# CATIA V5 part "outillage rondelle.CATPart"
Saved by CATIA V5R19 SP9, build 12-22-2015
Part number: outillage rondelle
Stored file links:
  Z:\fausse table rondelle-20220905T211342Z-001\fausse table rondelle\outillage rondelle.CATPart
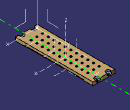
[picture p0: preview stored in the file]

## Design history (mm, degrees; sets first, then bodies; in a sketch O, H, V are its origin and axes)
AxisSystem1: origin (0, 0, 0), X (1, 0, 0), Y (0, 1, 0), Z (0, 0, 1)
AxisSystem2: origin (-48.5, -174, 0), X (1, 0, 0), Y (0, 1, 0), Z (0, 0, 1)
Set1 "GEOCN"
  Point1: (0, -3, 0), relative to vertex [face of Pad1 from Sketch1.L3 | face of Pad1 from Sketch1.L2 | start face of Pad1], in AxisSystem1
Body1 (main body)
  Sketch1 on XY plane of AxisSystem1, origin (0, 0, 0), H (1, 0, 0), V (0, 1, 0)
    line L1 (48.5, 171) -> (48.5, -171)
    line L2 (48.5, -171) -> (-48.5, -171)
    line L3 (-48.5, -171) -> (-48.5, 171)
    line L4 (-48.5, 171) -> (48.5, 171)
    distance L3 L1 = 97
    distance L4 L2 = 342
    vertical: L1 V, L3 V
    horizontal: L2 H, L4 H
    equidistance: L1 L3 O, L2 L4 O
  Pad1: profile Sketch1, direction (0, 0, 1), length 15
  Sketch2 on XY plane of AxisSystem1, origin (0, 0, 0), H (1, 0, 0), V (0, 1, 0)
    construction line L1 (-25, 173) -> (-25, 165)
    point P2 (-25, 165)
    line L2 (-21.9, 173) -> (-21.9, 165)
    line L3 (-28.1, 165) -> (-28.1, 173)
    arc A1 centre (-25, 165) radius 3.1 from (-21.9, 165) to (-28.1, 165) cw
    arc A2 centre (-25, 173) radius 3.1 from (-28.1, 173) to (-21.9, 173) cw
    construction line L4 (25, 173) -> (25, 165)
    point P8 (25, 165)
    line L5 (28.1, 173) -> (28.1, 165)
    line L6 (21.9, 165) -> (21.9, 173)
    arc A3 centre (25, 165) radius 3.1 from (28.1, 165) to (21.9, 165) cw
    arc A4 centre (25, 173) radius 3.1 from (21.9, 173) to (28.1, 173) cw
    construction line L7 (-25, -165) -> (-25, -173)
    point P13 (-25, -165)
    line L8 (-21.9, -165) -> (-21.9, -173)
    line L9 (-28.1, -173) -> (-28.1, -165)
    arc A5 centre (-25, -173) radius 3.1 from (-21.9, -173) to (-28.1, -173) cw
    arc A6 centre (-25, -165) radius 3.1 from (-28.1, -165) to (-21.9, -165) cw
    construction line L10 (25, -165) -> (25, -173)
    point P19 (25, -165)
    line L11 (28.1, -165) -> (28.1, -173)
    line L12 (21.9, -173) -> (21.9, -165)
    arc A7 centre (25, -173) radius 3.1 from (28.1, -173) to (21.9, -173) cw
    arc A8 centre (25, -165) radius 3.1 from (21.9, -165) to (28.1, -165) cw
    reference projected line E1 through (0, 0) direction (0, 1) from edge [YZ plane of AxisSystem1 | XY plane of AxisSystem1]
    reference projected line E2 through (0, 0) direction (0, 1) from edge [YZ plane of AxisSystem1 | XY plane of AxisSystem1]
    reference projected line E3 through (0, 0) direction (0, 1) from edge [YZ plane of AxisSystem1 | XY plane of AxisSystem1]
    reference projected line E4 through (0, 0) direction (0, 1) from edge [YZ plane of AxisSystem1 | XY plane of AxisSystem1]
    reference intersected line E5 (-48.5, 171) -> (48.5, 171) from face of Pad1 from Sketch1.L4
    reference intersected line E6 (-48.5, 171) -> (48.5, 171) from face of Pad1 from Sketch1.L4
    reference intersected line E7 (48.5, -171) -> (-48.5, -171) from face of Pad1 from Sketch1.L2
    reference intersected line E8 (48.5, -171) -> (-48.5, -171) from face of Pad1 from Sketch1.L2
    distance L1 L2 = 3.1
    distance L4 L5 = 3.1
    distance L7 L8 = 3.1
    distance L10 L11 = 3.1
    distance L7 E1 = 25
    distance L10 E2 = 25
    distance L1 E3 = 25
    distance L4 E4 = 25
    distance P2 E5 = 6
    distance P8 E6 = 6
    distance P19 E7 = 6
    distance P13 E8 = 6
    length L7 = 8
    length L10 = 8
    length L1 = 8
    length L4 = 8
    vertical: L1 V, L4 V, L7 V, L10 V
    tangency: A1 L2, A2 L2, A1 L3, A2 L3, A3 L5, A4 L5, A3 L6, A4 L6, A5 L8, A6 L8, A5 L9, A6 L9, A7 L11, A8 L11, A7 L12, A8 L12
  Pocket1: profile Sketch2, direction (0, 0, -1), through (limit type 6)
  Sketch3 on end face of Pad1, origin (0, 0, 15), H (1, 0, 0), V (0, 1, 0)
    construction line L1 (-25, 173) -> (-25, 165)
    point P2 (-25, 165)
    line L2 (-15, 173) -> (-15, 165)
    line L3 (-35, 165) -> (-35, 173)
    arc A1 centre (-25, 165) radius 10 from (-15, 165) to (-35, 165) cw
    arc A2 centre (-25, 173) radius 10 from (-35, 173) to (-15, 173) cw
    construction line L4 (25, 173) -> (25, 165)
    point P8 (25, 165)
    line L5 (35, 173) -> (35, 165)
    line L6 (15, 165) -> (15, 173)
    arc A3 centre (25, 165) radius 10 from (35, 165) to (15, 165) cw
    arc A4 centre (25, 173) radius 10 from (15, 173) to (35, 173) cw
    construction line L7 (25, -165) -> (25, -173)
    point P13 (25, -165)
    line L8 (35, -165) -> (35, -173)
    line L9 (15, -173) -> (15, -165)
    arc A5 centre (25, -173) radius 10 from (35, -173) to (15, -173) cw
    arc A6 centre (25, -165) radius 10 from (15, -165) to (35, -165) cw
    construction line L10 (-25, -165) -> (-25, -173)
    point P19 (-25, -165)
    line L11 (-15, -165) -> (-15, -173)
    line L12 (-35, -173) -> (-35, -165)
    arc A7 centre (-25, -173) radius 10 from (-15, -173) to (-35, -173) cw
    arc A8 centre (-25, -165) radius 10 from (-35, -165) to (-15, -165) cw
    reference projected point E1 (-25, 165) from axis of face of Pocket1 from Sketch2.A1
    reference projected point E2 (25, 165) from axis of face of Pocket1 from Sketch2.A3
    reference projected point E3 (-25, -165) from axis of face of Pocket1 from Sketch2.A6
    reference projected point E4 (25, -165) from axis of face of Pocket1 from Sketch2.A8
    distance L1 L2 = 10
    distance L4 L5 = 10
    distance L7 L8 = 10
    distance L10 L11 = 10
    length L7 = 8
    length L10 = 8
    length L4 = 8
    length L1 = 8
    vertical: L1 V, L4 V, L7 V, L10 V
    tangency: A1 L2, A2 L2, A1 L3, A2 L3, A3 L5, A4 L5, A3 L6, A4 L6, A5 L8, A6 L8, A5 L9, A6 L9, A7 L11, A8 L11, A7 L12, A8 L12
    coincidence: P2 E1, P8 E2, P19 E3, P13 E4
  Pocket2: profile Sketch3, direction (0, 0, -1), up to start face of Pad1, offset -7
  Sketch4 on XY plane of AxisSystem1, origin (0, 0, 0), H (1, 0, 0), V (0, 1, 0)
    construction line L1 (-27.9, -125) -> (-22.1, -125)
    line L2 (-27.9, -119.95) -> (-22.1, -119.95)
    line L3 (-22.1, -130.05) -> (-27.9, -130.05)
    arc A1 centre (-22.1, -125) radius 5.05 from (-22.1, -119.95) to (-22.1, -130.05) cw
    arc A2 centre (-27.9, -125) radius 5.05 from (-27.9, -130.05) to (-27.9, -119.95) cw
    point P7 (-25, -125)
    point P8 (-27.8868, -130)
    point P9 (-22.1132, -130)
    point P10 (-19.2265, -125)
    point P11 (-22.1132, -120)
    point P12 (-27.8868, -120)
    point P13 (-30.7735, -125)
    point P14 (-25, -130)
    construction line L4 (-27.8868, -130) -> (-22.1132, -130)
    construction line L5 (-22.1132, -130) -> (-19.2265, -125)
    construction line L6 (-19.2265, -125) -> (-22.1132, -120)
    construction line L7 (-22.1132, -120) -> (-27.8868, -120)
    construction line L8 (-27.8868, -120) -> (-30.7735, -125)
    construction line L9 (-30.7735, -125) -> (-27.8868, -130)
    construction line L10 (-25, -125) -> (-25, -130)
    construction circle A3 centre (-25, -125) radius 5.7735
    construction arc A4 centre (-27.8868, -120) radius 5.7735 from (-22.1132, -120) to (-30.7735, -125) cw
    construction arc A5 centre (-22.1132, -130) radius 5.7735 from (-19.2265, -125) to (-27.8868, -130) ccw
    reference projected line E1 through (0, 0) direction (0, 1) from edge [YZ plane of AxisSystem1 | XY plane of AxisSystem1]
    reference projected line E2 through (0, 0) direction (1, 0) from edge [XY plane of AxisSystem1 | ZX plane of AxisSystem1]
    distance L1 L2 = 5.05
    distance L4 L7 = 10
    length L1 = 5.8
    length L7 = 5.7735 (reference)
    distance E1 P7 = 25
    distance E2 P7 = 125
    horizontal: L1 H
    tangency: A1 L2, A2 L2, A1 L3, A2 L3
    vertical: L10 V
    coincidence: A3 P8, A3 P9, A3 P10, A3 P11, A3 P12, A3 P13, A4 P7, A5 P7
    midpoint: P14 L4, L1 P7
    parallelism: L4 L7
  Pocket3: profile Sketch4, direction (0, 0, 1), length 6
  Sketch5 on XY plane of AxisSystem1, origin (0, 0, 0), H (1, 0, 0), V (0, 1, 0)
    point P1 (-25, -125)
    reference projected line E1 through (0, 0) direction (0, 1) from edge [YZ plane of AxisSystem1 | XY plane of AxisSystem1]
    reference projected line E2 through (0, 0) direction (1, 0) from edge [XY plane of AxisSystem1 | ZX plane of AxisSystem1]
    distance P1 E1 = 25
    distance P1 E2 = 125
  Hole1: placed by Sketch5, at (-25, -125, 0) direction (0, 0, -1), diameter 6.2, through (limit type 6)
  Sketch6 on end face of Pad1, origin (-14.3209, -81.386, 15), H (1, 0, 0), V (0, 1, 0)
    point P1 (-10.6791, -43.614)
    reference projected point E1 (-10.6791, -43.614) from axis of face of Hole1
    coincidence: P1 E1
  Hole2: placed by Sketch6, at (-25, -125, 15) direction (0, 0, -1), diameter 8, depth 3
  RectPattern1: of Pocket3, Hole1, Hole2, direction 1 instances 3, spacing 25, along X axis, direction 2 instances 11, spacing 25, along Y axis
  Sketch7 on end face of Pad1, origin (0, 0, 15), H (1, 0, 0), V (0, 1, 0)
    construction line L1 (-53.5, 125) -> (-53.5, -125)
    point P1 (-53.5, 125)
    point P2 (-53.5, -125)
    line L2 (-47.5, 125) -> (-47.5, -125)
    line L3 (-59.5, -125) -> (-59.5, 125)
    arc A1 centre (-53.5, -125) radius 6 from (-47.5, -125) to (-59.5, -125) cw
    arc A2 centre (-53.5, 125) radius 6 from (-59.5, 125) to (-47.5, 125) cw
    reference intersected line E1 (-48.5, -171) -> (-48.5, 171) from face of Pad1 from Sketch1.L3
    reference projected line E2 through (0, 0) direction (1, 0) from edge [XY plane of AxisSystem1 | ZX plane of AxisSystem1]
    distance L1 L2 = 6
    distance L1 E1 = 5
    length L1 = 250
    vertical: L1 V
    tangency: A1 L2, A2 L2, A1 L3, A2 L3
    symmetry: P1 P2 E2
  Pocket4: profile Sketch7, direction (0, 0, -1), length 4
  Sketch8 on XY plane of AxisSystem1, origin (0, 0, 0), H (1, 0, 0), V (0, 1, 0)
    construction line L1 (52.5, 125) -> (52.5, -125)
    point P1 (52.5, 125)
    point P2 (52.5, -125)
    line L2 (58.5, 125) -> (58.5, -125)
    line L3 (46.5, -125) -> (46.5, 125)
    arc A1 centre (52.5, -125) radius 6 from (58.5, -125) to (46.5, -125) cw
    arc A2 centre (52.5, 125) radius 6 from (46.5, 125) to (58.5, 125) cw
    reference intersected line E1 (48.5, 171) -> (48.5, -171) from face of Pad1 from Sketch1.L1
    reference projected line E2 through (0, 0) direction (1, 0) from edge [XY plane of AxisSystem1 | ZX plane of AxisSystem1]
    distance L1 L2 = 6
    distance L1 E1 = 4
    length L1 = 250
    vertical: L1 V
    tangency: A1 L2, A2 L2, A1 L3, A2 L3
    symmetry: P2 P1 E2
  Pocket5: profile Sketch8, direction (0, 0, 1), length 4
